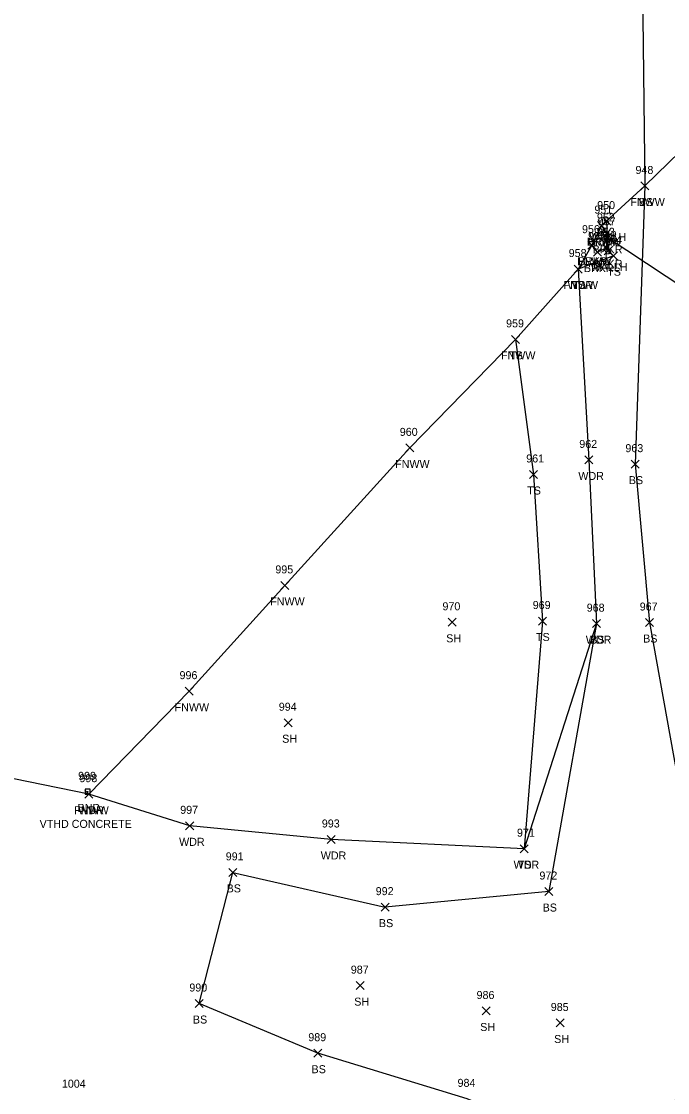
# Model space of a CAD drawing. Extents: x 1629176 to 1637209, y 606063 to 610167.
# Drawn here: x 1629750 to 1629911.4, y 607073 to 607340.7 of the extents above; entities that cross this region are included whole.
import ezdxf

# ---------------------------------------------------------------- set-up
doc = ezdxf.new("R2010")
doc.units = 0
for name, color, linetype in [('D_A', 7, 'Continuous'), ('D_I', 7, 'Continuous'), ('D_TIC', 7, 'Continuous'), ('DCP', 7, 'Continuous'), ('DHW', 7, 'Continuous'), ('L_A', 7, 'Continuous'), ('L_I', 7, 'Continuous'), ('L_TIC', 7, 'Continuous'), ('LAWA', 7, 'Continuous'), ('LAWE', 7, 'Continuous'), ('LELB', 7, 'Continuous'), ('LFNC', 7, 'Continuous'), ('M_A', 7, 'Continuous'), ('M_C', 7, 'Continuous'), ('M_I', 7, 'Continuous'), ('MHBP', 7, 'Continuous')]:
    doc.layers.add(name, color=color, linetype=linetype)

msp = doc.modelspace()

# ---------------------------------------------------------------- linework, layer by layer
at = {"layer": 'D_TIC'}
for points in [[(1629895.22, 607289.78), (1629897.22, 607291.78)], [(1629897.22, 607289.78), (1629895.22, 607291.78)], [(1629895.28, 607285.71), (1629897.28, 607287.71)], [(1629897.28, 607285.71), (1629895.28, 607287.71)], [(1629895.55, 607282.32), (1629897.55, 607284.32)], [(1629897.55, 607282.32), (1629895.55, 607284.32)]]:
    msp.add_lwpolyline(points, dxfattribs=at)
at = {"layer": 'DCP'}
msp.add_lwpolyline([(1630117.03, 607140.65), (1629896.28, 607286.71)], dxfattribs=at)
at = {"layer": 'DHW'}
msp.add_lwpolyline([(1629896.55, 607283.32), (1629896.22, 607290.78)], dxfattribs=at)
at = {"layer": 'L_TIC'}
for points in [[(1629904.7, 607298.56), (1629906.7, 607300.56)], [(1629906.7, 607298.56), (1629904.7, 607300.56)], [(1629904.7, 607298.56), (1629906.7, 607300.56)], [(1629906.7, 607298.56), (1629904.7, 607300.56)], [(1629893.86, 607288.64), (1629895.86, 607290.64)], [(1629895.86, 607288.64), (1629893.86, 607290.64)], [(1629893.86, 607288.64), (1629895.86, 607290.64)], [(1629895.86, 607288.64), (1629893.86, 607290.64)], [(1629895.07, 607286.71), (1629897.07, 607288.71)], [(1629897.07, 607286.71), (1629895.07, 607288.71)], [(1629891.4, 607283.76), (1629893.4, 607285.76)], [(1629893.4, 607283.76), (1629891.4, 607285.76)], [(1629891.4, 607283.76), (1629893.4, 607285.76)], [(1629893.4, 607283.76), (1629891.4, 607285.76)], [(1629892.86, 607282.04), (1629894.86, 607284.04)], [(1629894.86, 607282.04), (1629892.86, 607284.04)], [(1629895.06, 607283.11), (1629897.06, 607285.11)], [(1629897.06, 607283.11), (1629895.06, 607285.11)], [(1629896.87, 607281.13), (1629898.87, 607283.13)], [(1629898.87, 607281.13), (1629896.87, 607283.13)], [(1629888.02, 607277.8), (1629890.02, 607279.8)], [(1629890.02, 607277.8), (1629888.02, 607279.8)], [(1629888.02, 607277.8), (1629890.02, 607279.8)], [(1629890.02, 607277.8), (1629888.02, 607279.8)], [(1629888.02, 607277.8), (1629890.02, 607279.8)], [(1629890.02, 607277.8), (1629888.02, 607279.8)], [(1629872.39, 607260.22), (1629874.39, 607262.22)], [(1629874.39, 607260.22), (1629872.39, 607262.22)], [(1629872.39, 607260.22), (1629874.39, 607262.22)], [(1629874.39, 607260.22), (1629872.39, 607262.22)], [(1629845.96, 607233.11), (1629847.96, 607235.11)], [(1629847.96, 607233.11), (1629845.96, 607235.11)], [(1629890.71, 607230.09), (1629892.71, 607232.09)], [(1629892.71, 607230.09), (1629890.71, 607232.09)], [(1629902.23, 607229.04), (1629904.23, 607231.04)], [(1629904.23, 607229.04), (1629902.23, 607231.04)], [(1629876.89, 607226.46), (1629878.89, 607228.46)], [(1629878.89, 607226.46), (1629876.89, 607228.46)], [(1629814.75, 607198.74), (1629816.75, 607200.74)], [(1629816.75, 607198.74), (1629814.75, 607200.74)], [(1629856.58, 607189.52), (1629858.58, 607191.52)], [(1629858.58, 607189.52), (1629856.58, 607191.52)], [(1629879.1, 607189.84), (1629881.1, 607191.84)], [(1629881.1, 607189.84), (1629879.1, 607191.84)], [(1629892.57, 607189.18), (1629894.57, 607191.18)], [(1629894.57, 607189.18), (1629892.57, 607191.18)], [(1629892.57, 607189.18), (1629894.57, 607191.18)], [(1629894.57, 607189.18), (1629892.57, 607191.18)], [(1629905.81, 607189.46), (1629907.81, 607191.46)], [(1629907.81, 607189.46), (1629905.81, 607191.46)], [(1629790.88, 607172.31), (1629792.88, 607174.31)], [(1629792.88, 607172.31), (1629790.88, 607174.31)], [(1629815.61, 607164.42), (1629817.61, 607166.42)], [(1629817.61, 607164.42), (1629815.61, 607166.42)], [(1629765.82, 607146.57), (1629767.82, 607148.57)], [(1629767.82, 607146.57), (1629765.82, 607148.57)], [(1629765.82, 607146.57), (1629767.82, 607148.57)], [(1629767.82, 607146.57), (1629765.82, 607148.57)], [(1629790.99, 607138.66), (1629792.99, 607140.66)], [(1629792.99, 607138.66), (1629790.99, 607140.66)], [(1629826.37, 607135.25), (1629828.37, 607137.25)], [(1629828.37, 607135.25), (1629826.37, 607137.25)], [(1629874.54, 607132.94), (1629876.54, 607134.94)], [(1629876.54, 607132.94), (1629874.54, 607134.94)], [(1629874.54, 607132.94), (1629876.54, 607134.94)], [(1629876.54, 607132.94), (1629874.54, 607134.94)], [(1629801.79, 607127.03), (1629803.79, 607129.03)], [(1629803.79, 607127.03), (1629801.79, 607129.03)], [(1629880.71, 607122.24), (1629882.71, 607124.24)], [(1629882.71, 607122.24), (1629880.71, 607124.24)], [(1629839.82, 607118.34), (1629841.82, 607120.34)], [(1629841.82, 607118.34), (1629839.82, 607120.34)], [(1629839.82, 607118.34), (1629841.82, 607120.34)], [(1629841.82, 607118.34), (1629839.82, 607120.34)], [(1629833.6, 607098.73), (1629835.6, 607100.73)], [(1629835.6, 607098.73), (1629833.6, 607100.73)], [(1629793.36, 607094.25), (1629795.36, 607096.25)], [(1629795.36, 607094.25), (1629793.36, 607096.25)], [(1629865.07, 607092.39), (1629867.07, 607094.39)], [(1629867.07, 607092.39), (1629865.07, 607094.39)], [(1629883.54, 607089.39), (1629885.54, 607091.39)], [(1629885.54, 607089.39), (1629883.54, 607091.39)], [(1629822.99, 607081.84), (1629824.99, 607083.84)], [(1629824.99, 607081.84), (1629822.99, 607083.84)]]:
    msp.add_lwpolyline(points, dxfattribs=at)
at = {"layer": 'LAWA'}
msp.add_lwpolyline([(1629889.02, 607278.8), (1629891.71, 607231.09), (1629893.57, 607190.18), (1629875.54, 607133.94), (1629827.37, 607136.25), (1629791.99, 607139.66), (1629766.82, 607147.57)], dxfattribs=at)
at = {"layer": 'LAWE'}
msp.add_lwpolyline([(1629894.86, 607289.64), (1629896.07, 607287.71), (1629896.06, 607284.11), (1629893.86, 607283.04), (1629892.4, 607284.76)], dxfattribs=at)
at = {"layer": 'LELB'}
for points in [[(1629872.74, 607605.4), (1629887.91, 607617.06), (1629901.2, 607617.32), (1629908.5, 607605.8), (1629913.9, 607581.78), (1629917.02, 607546.87), (1629916.16, 607509.81), (1629923.16, 607493.27), (1629925.16, 607453.58), (1629924.47, 607424.14), (1629903.61, 607389.66), (1629905.12, 607348.76), (1629905.7, 607299.56), (1629903.23, 607230.04), (1629906.81, 607190.46), (1629918.09, 607128.12), (1629917.39, 607086.84), (1629912.31, 607067.56), (1629894.57, 607057.72), (1629861.26, 607071.43), (1629823.99, 607082.84), (1629794.36, 607095.25), (1629802.79, 607128.03), (1629840.82, 607119.34)], [(1629897.87, 607282.13), (1629889.02, 607278.8)], [(1629873.39, 607261.22), (1629877.89, 607227.46), (1629880.1, 607190.84), (1629875.54, 607133.94)], [(1629893.57, 607190.18), (1629881.71, 607123.24), (1629840.82, 607119.34)]]:
    msp.add_lwpolyline(points, dxfattribs=at)
at = {"layer": 'LFNC'}
msp.add_lwpolyline([(1629932.18, 607325.29), (1629905.7, 607299.56), (1629894.86, 607289.64), (1629892.4, 607284.76), (1629889.02, 607278.8), (1629873.39, 607261.22), (1629846.96, 607234.11), (1629815.75, 607199.74), (1629791.88, 607173.31), (1629766.82, 607147.57), (1629732.92, 607154.51), (1629676.65, 607165.93), (1629624.92, 607174.61), (1629584.57, 607180.8), (1629561.91, 607184.66)], dxfattribs=at)
at = {"layer": 'MHBP'}
for p, q in [((1629767.15, 607148.8), (1629765.9, 607148.8)), ((1629765.9, 607148.8), (1629765.9, 607147.55)), ((1629767.15, 607148.8), (1629765.9, 607148.8)), ((1629765.9, 607148.8), (1629765.9, 607147.55)), ((1629767.15, 607147.55), (1629767.15, 607148.8)), ((1629767.15, 607147.55), (1629767.15, 607148.8)), ((1629765.9, 607147.55), (1629767.15, 607147.55)), ((1629765.9, 607147.55), (1629767.15, 607147.55))]:
    msp.add_line(p, q, dxfattribs=at)
msp.add_circle((1629766.5, 607148.14), 0.0833, dxfattribs=at)

# ---------------------------------------------------------------- texts
at = {"layer": 'D_A'}
for s, p in [('WALLH', (1629891.81, 607285.78)), ('P', (1629895.66, 607281.71)), ('WALLH', (1629892.14, 607278.32))]:
    msp.add_text(s, height=2, dxfattribs=at).set_placement(p)
at = {"layer": 'D_I'}
for s, p in [('950', (1629893.77, 607293.78)), ('957', (1629893.91, 607289.71)), ('949', (1629894.18, 607286.32))]:
    msp.add_text(s, height=2, dxfattribs=at).set_placement(p)
at = {"layer": 'L_A'}
for s, p in [('FNWW', (1629902.05, 607294.56)), ('BS', (1629904.14, 607294.56)), ('FNWW', (1629891.21, 607284.64)), ('BRKR', (1629891.45, 607284.64)), ('BRKR', (1629892.66, 607282.71)), ('FNWW', (1629888.75, 607279.76)), ('BRKR', (1629888.99, 607279.76)), ('BRKR', (1629890.45, 607278.04)), ('BRKR', (1629892.65, 607279.11)), ('TS', (1629896.28, 607277.13)), ('FNWW', (1629885.37, 607273.8)), ('WDR', (1629886.38, 607273.8)), ('TS', (1629887.43, 607273.8)), ('FNWW', (1629869.74, 607256.22)), ('TS', (1629871.8, 607256.22)), ('FNWW', (1629843.31, 607229.11)), ('WDR', (1629889.07, 607226.09)), ('BS', (1629901.67, 607225.04)), ('TS', (1629876.3, 607222.46)), ('FNWW', (1629812.1, 607194.74)), ('SH', (1629856.07, 607185.52)), ('TS', (1629878.5, 607185.84)), ('WDR', (1629890.93, 607185.18)), ('BS', (1629892.01, 607185.18)), ('BS', (1629905.25, 607185.46)), ('FNWW', (1629788.23, 607168.31)), ('SH', (1629815.1, 607160.42)), ('FNWW', (1629763.17, 607142.57)), ('WDR', (1629764.18, 607142.57)), ('WDR', (1629789.35, 607134.66)), ('WDR', (1629824.73, 607131.25)), ('WDR', (1629872.9, 607128.94)), ('TS', (1629873.95, 607128.94)), ('BS', (1629801.23, 607123.03)), ('BS', (1629880.15, 607118.24)), ('BS', (1629839.26, 607114.34)), ('BS', (1629839.26, 607114.34)), ('SH', (1629833.09, 607094.73)), ('BS', (1629792.8, 607090.25)), ('SH', (1629864.56, 607088.39)), ('SH', (1629883.03, 607085.39)), ('BS', (1629822.43, 607077.84))]:
    msp.add_text(s, height=2, dxfattribs=at).set_placement(p)
at = {"layer": 'L_I'}
for s, p in [('948', (1629903.34, 607302.56)), ('948', (1629903.34, 607302.56)), ('951', (1629893.07, 607292.64)), ('951', (1629893.07, 607292.64)), ('952', (1629893.71, 607290.71)), ('956', (1629889.98, 607287.76)), ('956', (1629889.98, 607287.76)), ('955', (1629891.5, 607286.04)), ('953', (1629893.7, 607287.11)), ('954', (1629895.5, 607285.13)), ('958', (1629886.66, 607281.8)), ('958', (1629886.66, 607281.8)), ('958', (1629886.66, 607281.8)), ('959', (1629871.02, 607264.22)), ('959', (1629871.02, 607264.22)), ('960', (1629844.47, 607237.11)), ('962', (1629889.3, 607234.09)), ('963', (1629900.82, 607233.04)), ('961', (1629876.05, 607230.46)), ('995', (1629813.39, 607202.74)), ('970', (1629855.13, 607193.52)), ('969', (1629877.68, 607193.84)), ('968', (1629891.16, 607193.18)), ('968', (1629891.16, 607193.18)), ('967', (1629904.4, 607193.46)), ('996', (1629789.46, 607176.31)), ('994', (1629814.25, 607168.42)), ('998', (1629764.46, 607150.57)), ('998', (1629764.46, 607150.57)), ('997', (1629789.63, 607142.66)), ('993', (1629825, 607139.25)), ('971', (1629873.74, 607136.94)), ('971', (1629873.74, 607136.94)), ('991', (1629801, 607131.03)), ('972', (1629879.35, 607126.24)), ('992', (1629838.46, 607122.34)), ('992', (1629838.46, 607122.34)), ('987', (1629832.24, 607102.73)), ('990', (1629791.91, 607098.25)), ('986', (1629863.65, 607096.39)), ('985', (1629882.18, 607093.39)), ('989', (1629821.62, 607085.84)), ('984', (1629858.9, 607074.43)), ('1004', (1629760.07, 607074.22))]:
    msp.add_text(s, height=2, dxfattribs=at).set_placement(p)
at = {"layer": 'M_A'}
msp.add_text('BND', height=2, dxfattribs=at).set_placement((1629763.99, 607143.15))
at = {"layer": 'M_C'}
msp.add_text('VTHD CONCRETE', height=2, dxfattribs=at).set_placement((1629754.51, 607139.15))
at = {"layer": 'M_I'}
msp.add_text('999', height=2, dxfattribs=at).set_placement((1629764.13, 607151.15))

doc.saveas('drawing.dxf')
